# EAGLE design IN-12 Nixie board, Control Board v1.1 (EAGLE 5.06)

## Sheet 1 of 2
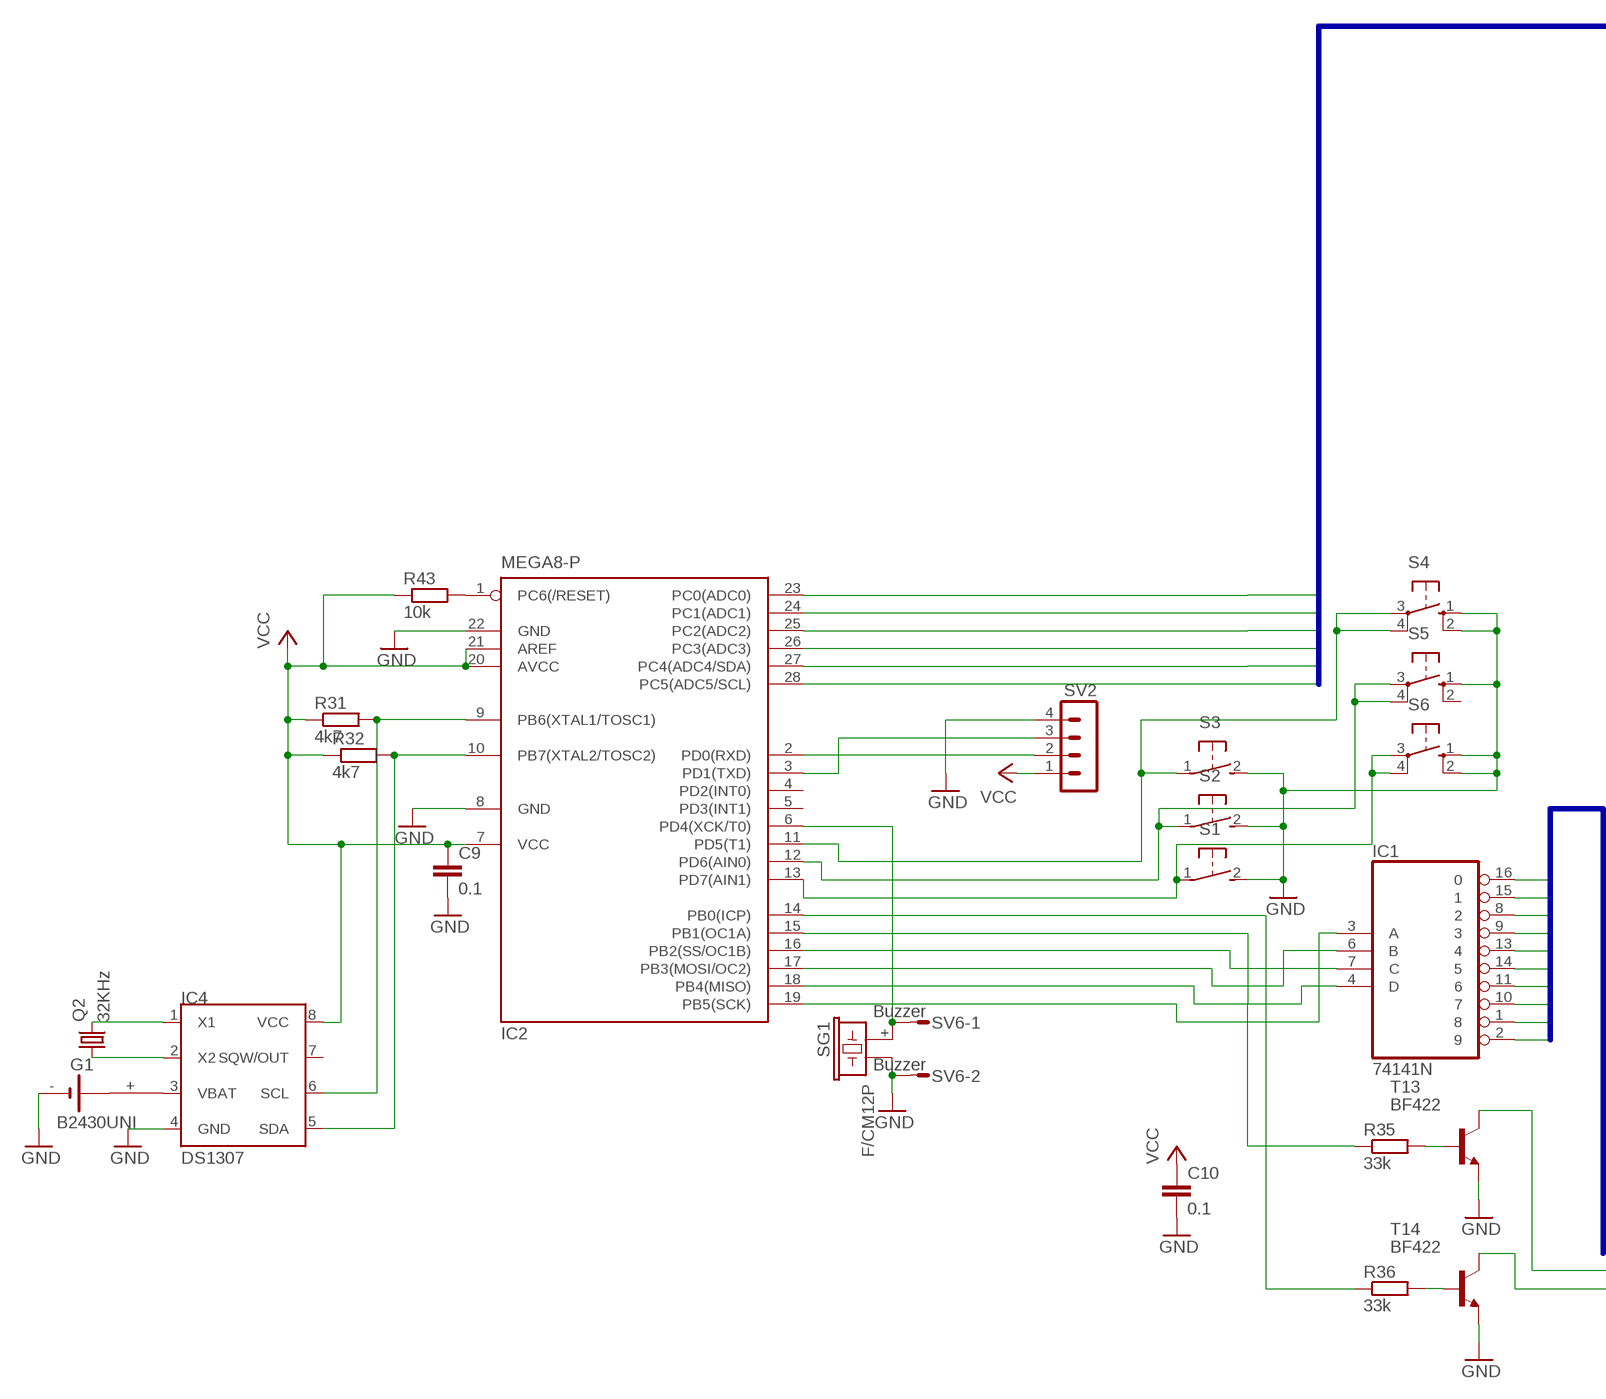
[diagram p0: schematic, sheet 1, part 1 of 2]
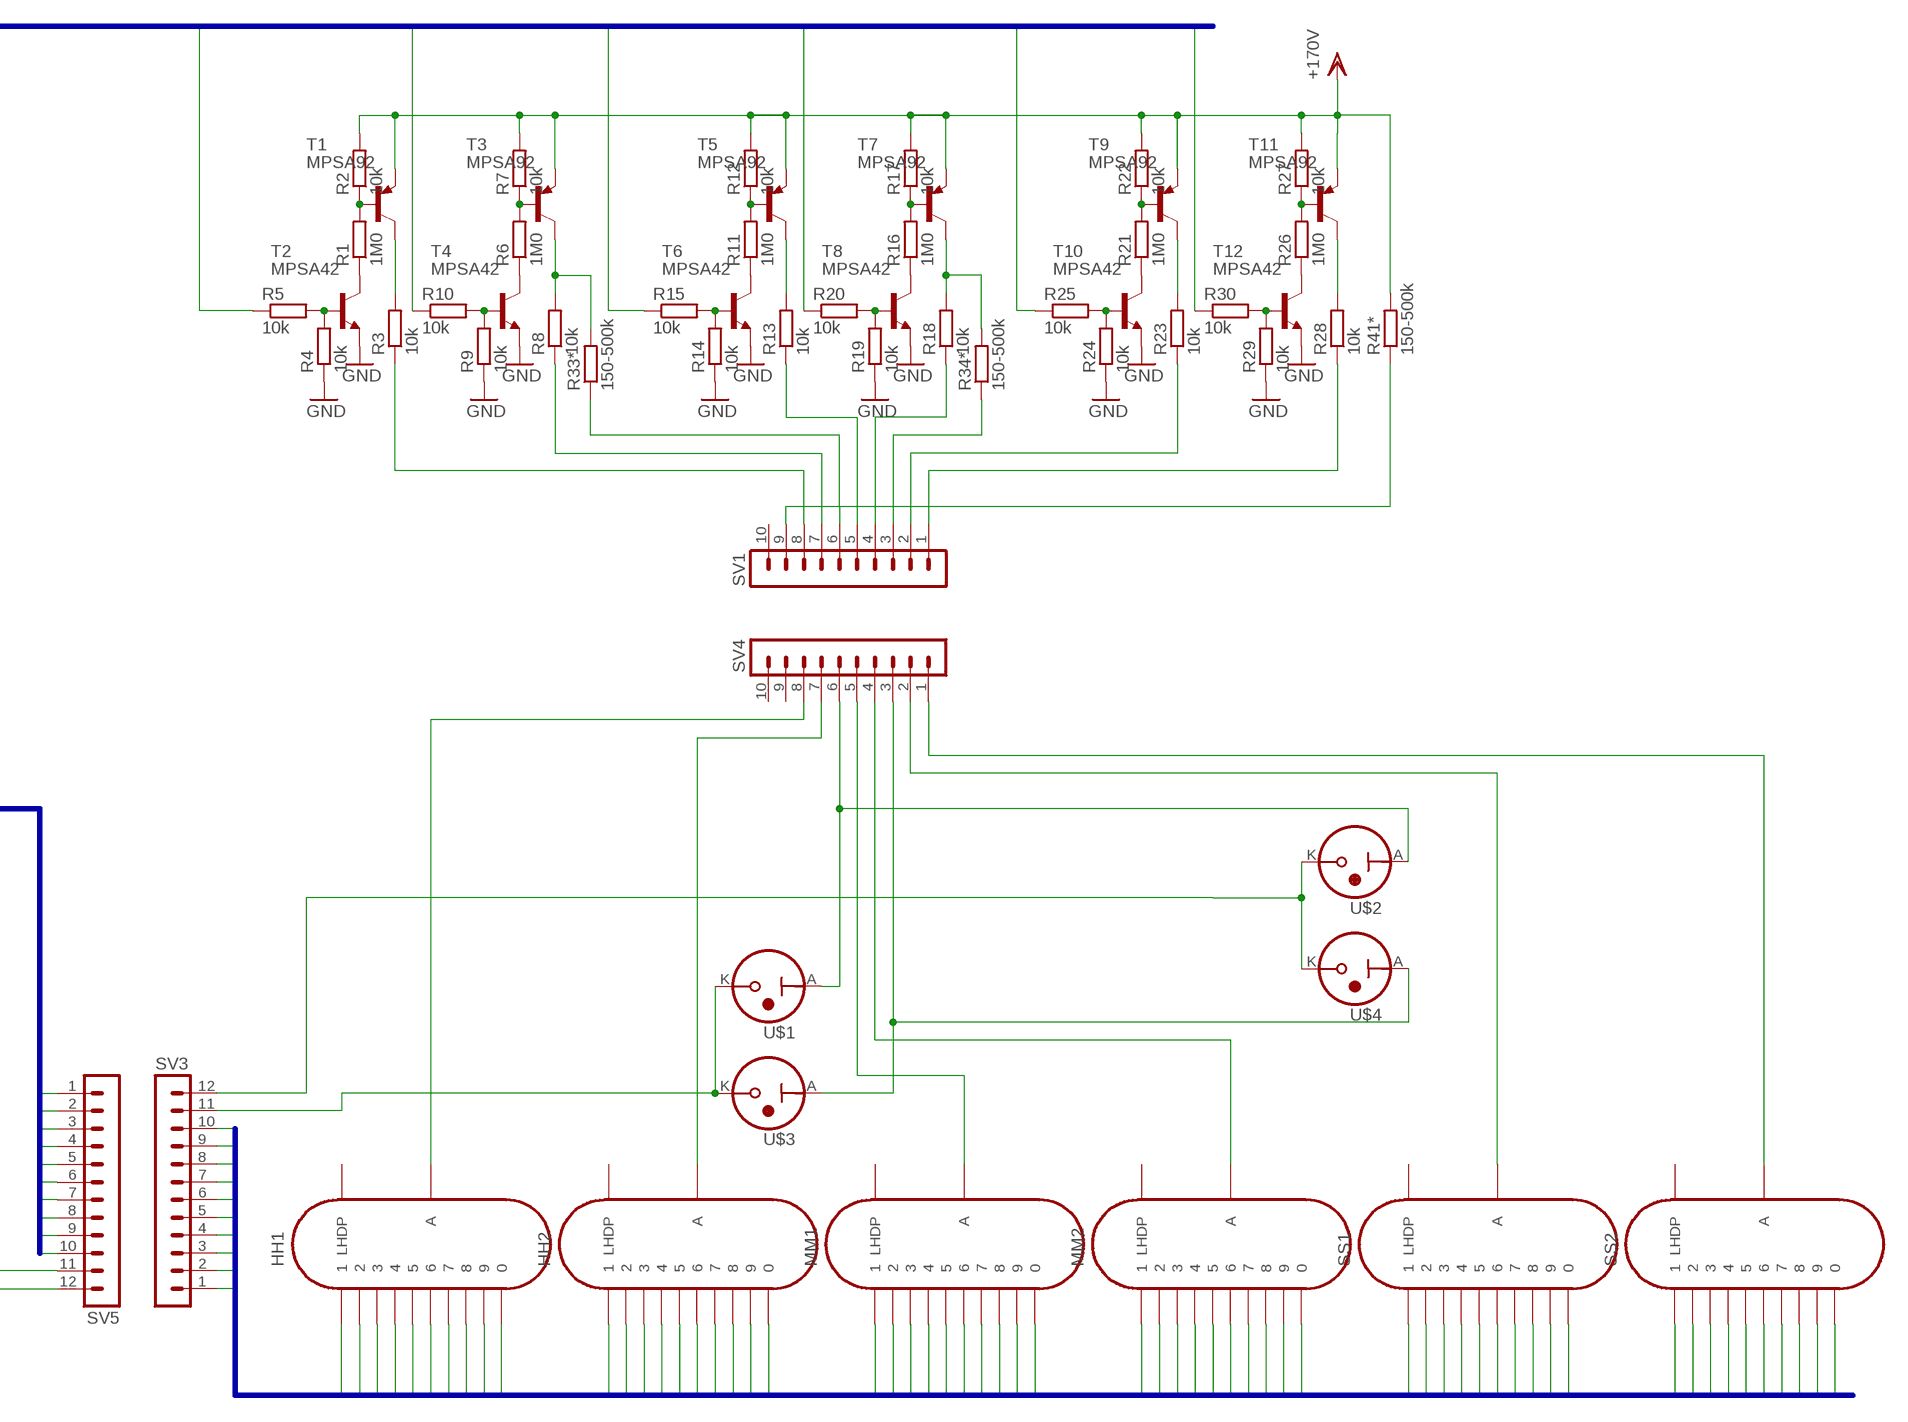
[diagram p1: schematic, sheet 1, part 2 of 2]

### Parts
C9  0.1  C-EUC1206  [C1206]
C10  0.1  C-EUC1206  [C1206]
G1  B2430UNI  [B2430UNI]
HH1  IN-12B  [IN-12]
HH2  IN-12B  [IN-12]
IC1  74141N  [DIL16]
IC2  MEGA8-P  [DIL28-3]
IC4  DS1307  [SOIC-8]
MM1  IN-12B  [IN-12]
MM2  IN-12B  [IN-12]
Q2  32KHz  CRYSTALTC26H  [TC26H]
R1  1M0  R-EU_R1206  [R1206]
R2  10k  R-EU_R1206  [R1206]
R3  10k  R-EU_R1206  [R1206]
R4  10k  R-EU_R1206  [R1206]
R5  10k  R-EU_R1206  [R1206]
R6  1M0  R-EU_R1206  [R1206]
R7  10k  R-EU_R1206  [R1206]
R8  10k  R-EU_R1206  [R1206]
R9  10k  R-EU_R1206  [R1206]
R10  10k  R-EU_R1206  [R1206]
R11  1M0  R-EU_R1206  [R1206]
R12  10k  R-EU_R1206  [R1206]
R13  10k  R-EU_R1206  [R1206]
R14  10k  R-EU_R1206  [R1206]
R15  10k  R-EU_R1206  [R1206]
R16  1M0  R-EU_R1206  [R1206]
R17  10k  R-EU_R1206  [R1206]
R18  10k  R-EU_R1206  [R1206]
R19  10k  R-EU_R1206  [R1206]
R20  10k  R-EU_R1206  [R1206]
R21  1M0  R-EU_R1206  [R1206]
R22  10k  R-EU_R1206  [R1206]
R23  10k  R-EU_R1206  [R1206]
R24  10k  R-EU_R1206  [R1206]
R25  10k  R-EU_R1206  [R1206]
R26  1M0  R-EU_R1206  [R1206]
R27  10k  R-EU_R1206  [R1206]
R28  10k  R-EU_R1206  [R1206]
R29  10k  R-EU_R1206  [R1206]
R30  10k  R-EU_R1206  [R1206]
R31  4k7  R-EU_R1206  [R1206]
R32  4k7  R-EU_R1206  [R1206]
R33*  150-500k  R-EU_R1206  [R1206]
R34*  150-500k  R-EU_R1206  [R1206]
R35  33k  R-EU_R1206  [R1206]
R36  33k  R-EU_R1206  [R1206]
R41*  150-500k  R-EU_R1206  [R1206]
R43  10k  R-EU_R1206  [R1206]
S1  31-XX  [B3F-31XX]
S2  31-XX  [B3F-31XX]
S3  31-XX  [B3F-31XX]
S4  10-XX  [B3F-10XX]
S5  10-XX  [B3F-10XX]
S6  10-XX  [B3F-10XX]
SG1  F/CM12P  [F/CM12P]
SS1  IN-12B  [IN-12]
SS2  IN-12B  [IN-12]
SV1  MA10-1  [MA10-1]
SV2  MA04-1  [MA04-1]
SV3  MA12-1  [MA12-1]
SV4  MA10-1  [MA10-1]
SV5  MA12-1  [MA12-1]
SV6  Buzzer  S02P  [S02P]
T1  MPSA92  MPSA63  [TO92-CBE]
T2  MPSA42  MPSA42-NPN-TO92-CBE  [TO92-CBE]
T3  MPSA92  MPSA63  [TO92-CBE]
T4  MPSA42  MPSA42-NPN-TO92-CBE  [TO92-CBE]
T5  MPSA92  MPSA63  [TO92-CBE]
T6  MPSA42  MPSA42-NPN-TO92-CBE  [TO92-CBE]
T7  MPSA92  MPSA63  [TO92-CBE]
T8  MPSA42  MPSA42-NPN-TO92-CBE  [TO92-CBE]
T9  MPSA92  MPSA63  [TO92-CBE]
T10  MPSA42  MPSA42-NPN-TO92-CBE  [TO92-CBE]
T11  MPSA92  MPSA63  [TO92-CBE]
T12  MPSA42  MPSA42-NPN-TO92-CBE  [TO92-CBE]
T13  BF422  BF422-NPN-TO92-BCE  [TO92-BCE]
T14  BF422  BF422-NPN-TO92-BCE  [TO92-BCE]
U$1  IN-3  [IN-3]
U$2  IN-3  [IN-3]
U$3  IN-3  [IN-3]
U$4  IN-3  [IN-3]

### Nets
0: IC1.8 SV5.10
1: IC1.2 SV5.9
2: IC1.1 SV5.8
3: IC1.9 SV5.7
4: IC1.10 SV5.6
5: IC1.11 SV5.5
6: IC1.13 SV5.4
7: IC1.14 SV5.3
8: IC1.15 SV5.2
9: IC1.16 SV5.1
$NEON1: SV5.11 T13.C
$NEON2: SV5.12 T14.C
GND: C9.2 C10.2 G1.- IC2.8(GND) IC2.22(GND) IC4.4(GND) R4.1 R9.1 R14.1 R19.1 R24.1 R29.1 S1.2(S) S2.2(S) S3.2(S) S4.1(S) S4.2(S1) S5.1(S) S6.1(S) S6.2(S1) SG1.- SV2.4 SV6.2 T2.E T4.E T6.E T8.E T10.E T12.E T13.E T14.E ; also sheet 2
H1: IC2.26(PC3(ADC3)) R5.1
H2: IC2.27(PC4(ADC4/SDA)) R10.1
L0: HH1.0 HH2.0 MM1.0 MM2.0 SS1.0 SS2.0 SV3.10
L1: HH1.1 HH2.1 MM1.1 MM2.1 SS1.1 SS2.1 SV3.9
L2: HH1.2 HH2.2 MM1.2 MM2.2 SS1.2 SS2.2 SV3.8
L3: HH1.3 HH2.3 MM1.3 MM2.3 SS1.3 SS2.3 SV3.7
L4: HH1.4 HH2.4 MM1.4 MM2.4 SS1.4 SS2.4 SV3.6
L5: HH1.5 HH2.5 MM1.5 MM2.5 SS1.5 SS2.5 SV3.5
L6: HH1.6 HH2.6 MM1.6 MM2.6 SS1.6 SS2.6 SV3.4
L7: HH1.7 HH2.7 MM1.7 MM2.7 SS1.7 SS2.7 SV3.3
L8: HH1.8 HH2.8 MM1.8 MM2.8 SS1.8 SS2.8 SV3.2
L9: HH1.9 HH2.9 MM1.9 MM2.9 SS1.9 SS2.9 SV3.1
M1: IC2.28(PC5(ADC5/SCL)) R15.1
M2: IC2.25(PC2(ADC2)) R20.1
N$1: R36.2 T14.B
N$2: R35.2 T13.B
N$3: R28.1 SV1.1
N$4: IC2.14(PB0(ICP)) R36.1
N$5: IC2.15(PB1(OC1A)) R35.1
N$13: SV4.6 U$1.A U$2.A
N$14: MM2.A SV4.4
N$15: SS1.A SV4.2
N$16: MM1.A SV4.5
N$17: R3.2 T1.C
N$18: HH2.A SV4.7
N$20: R1.2 R2.1 T1.B
N$21: R1.1 T2.C
N$22: R4.2 R5.2 T2.B
N$23: HH1.A SV4.8
N$24: R8.2 R33*.2 T3.C
N$25: R6.2 R7.1 T3.B
N$26: R6.1 T4.C
N$27: R9.2 R10.2 T4.B
N$28: R23.1 SV1.2
N$29: R13.2 T5.C
N$30: R11.2 R12.1 T5.B
N$31: R11.1 T6.C
N$32: R14.2 R15.2 T6.B
N$33: SS2.A SV4.1
N$34: R41*.1 SV1.9
N$35: R16.2 R17.1 T7.B
N$36: R16.1 T8.C
N$37: R19.2 R20.2 T8.B
N$38: R34*.1 SV1.3
N$39: R23.2 T9.C
N$40: R21.2 R22.1 T9.B
N$41: R21.1 T10.C
N$42: R24.2 R25.2 T10.B
N$43: R18.1 SV1.4
N$44: R28.2 T11.C
N$45: R26.2 R27.1 T11.B
N$46: R26.1 T12.C
N$47: R29.2 R30.2 T12.B
N$49: R13.1 SV1.5
N$51: SV4.3 U$3.A U$4.A
N$52: R8.1 SV1.7
N$53: R3.1 SV1.8
N$54: IC2.2(PD0(RXD)) SV2.2
N$55: IC2.3(PD1(TXD)) SV2.3
N$56: IC2.13(PD7(AIN1)) S1.1(P) S6.3(P) S6.4(P1)
N$57: IC2.12(PD6(AIN0)) S2.1(P) S5.3(P) S5.4(P1)
N$58: IC2.11(PD5(T1)) S3.1(P) S4.3(P) S4.4(P1)
N$59: IC1.7(C) IC2.16(PB2(SS/OC1B))
N$60: IC1.6(B) IC2.17(PB3(MOSI/OC2))
N$61: IC1.4(D) IC2.18(PB4(MISO))
N$62: IC1.3(A) IC2.19(PB5(SCK))
N$63: IC2.10(PB7(XTAL2/TOSC2)) IC4.5(SDA) R32.2
N$64: IC2.9(PB6(XTAL1/TOSC1)) IC4.6(SCL) R31.2
N$65: IC4.1(X1) Q2.2
N$66: IC4.2(X2) Q2.1
N$67: G1.+ IC4.3(VBAT)
N$68: R33*.1 SV1.6
N$71: IC2.6(PD4(XCK/T0)) SG1.+ SV6.1
N$72: R18.2 R34*.2 T7.C
N$90: IC2.1(PC6(/RESET)) R43.2
NEON1: SV3.12 U$2.K U$4.K
NEON2: SV3.11 U$1.K U$3.K
S1: IC2.24(PC1(ADC1)) R25.1
S2: IC2.23(PC0(ADC0)) R30.1
VCC: C9.1 C10.1 IC2.7(VCC) IC2.20(AVCC) IC2.21(AREF) IC4.8(VCC) R31.1 R32.1 R43.1 SV2.1 ; also sheet 2
VDD: R2.2 R7.2 R12.2 R17.2 R22.2 R27.2 R41*.2 T1.E T3.E T5.E T7.E T9.E T11.E ; supply symbol labelled +170V ; also sheet 2
Unconnected: G1.+@1(+) G1.+@2(+) G1.+@3(+) G1.+@4(+) G1.-@1(-) HH1.LHDP HH2.LHDP IC2.4(PD2(INT0)) IC2.5(PD3(INT1)) IC4.7(SQW/OUT) MM1.LHDP MM2.LHDP S5.2(S1) SS1.LHDP SS2.LHDP SV1.10 SV4.9 SV4.10

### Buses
H1,H2,M1,M2,S1,S2
0,1,2,3,4,5,6,7,8,9,L1,L2
L0,L1,L2,L3,L4,L5,L6,L7,L8,L9

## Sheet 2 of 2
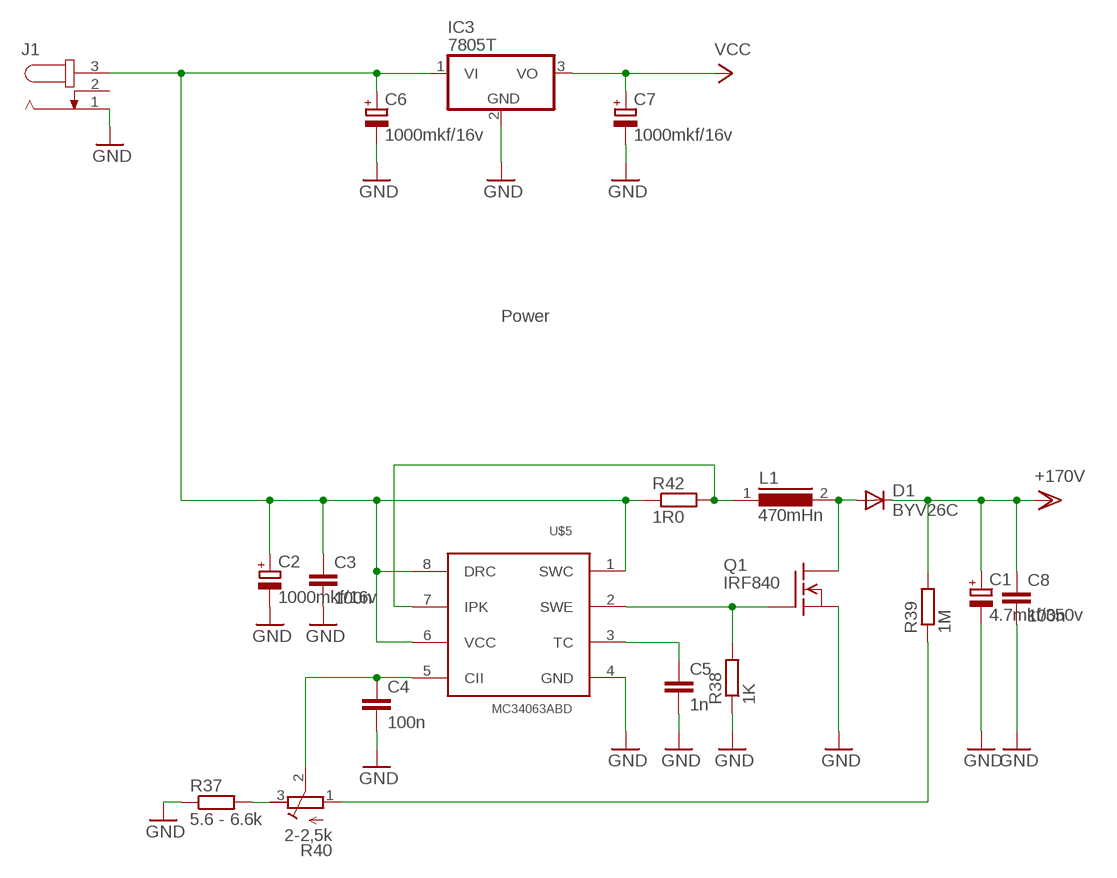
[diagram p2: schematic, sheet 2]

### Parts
C1  4.7mkf/350v  CPOL-EUE5-10.5  [E5-10,5]
C2  1000mkf/16v  CPOL-EUE5-8.5  [E5-8,5]
C3  100n  C-EU050-025X075  [C050-025X075]
C4  100n  C-EU050-025X075  [C050-025X075]
C5  1n  C-EU050-025X075  [C050-025X075]
C6  1000mkf/16v  CPOL-EUE5-8.5  [E5-8,5]
C7  1000mkf/16v  CPOL-EUE5-8.5  [E5-8,5]
C8  100n  C-EU050-025X075  [C050-025X075]
D1  BYV26C  BYV28  [SOD64-10]
IC3  7805T  [TO220H]
J1  JACK-PLUG1  [SPC4078]
L1  470mHn  B82131  [SUKW1-17]
Q1  IRF840  [TO220]
R37  5.6 - 6.6k  R-EU_R3216  [R3216]
R38  1K  R-EU_R3216  [R3216]
R39  1M  R-EU_R3216  [R3216]
R40  2-2,5k  R-TRIMM3339P  [RTRIM3339P]
R42  1R0  R-EU_M2309  [M2309]
U$5  MC34063ABD  [SO08]

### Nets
GND: C1.- C2.- C3.2 C4.2 C5.2 C6.- C7.- C8.2 IC3.2(GND) J1.1 Q1.3(S) R37.1 R38.1 U$5.4(GND) ; also sheet 1
N$6: C4.1 R40.2(S) U$5.5(CII)
N$8: Q1.1(G) R38.2 U$5.2(SWE)
N$9: C5.1 U$5.3(TC)
N$12: L1.1 R42.2 U$5.7(IPK)
N$48: R37.2 R40.3(A)
N$50: R39.1 R40.1(E)
N$92: D1.A L1.2 Q1.2(D)
VCC: C7.+ IC3.3(VO) ; also sheet 1
VCC+12: C2.+ C3.1 C6.+ IC3.1(VI) J1.3 R42.1 U$5.1(SWC) U$5.6(VCC) U$5.8(DRC)
VDD: C1.+ C8.1 D1.C R39.2 ; supply symbol labelled +170V ; also sheet 1
Unconnected: J1.2

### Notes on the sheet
- Power

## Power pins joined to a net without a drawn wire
GND: IC1.12(GND)
VCC: IC1.5(VCC)

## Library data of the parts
C1 C2 C6 C7 = rcl:CPOL-EU: POLARIZED CAPACITOR, European symbol
C3-C5 C8 = rcl:C-EU: CAPACITOR, European symbol
C9 C10 = resistor:C-EU: CAPACITOR, European symbol
D1 = diode:BYV28: DIODE
G1 = battery:B2430UNI: LI BATTERY
HH1 HH2 MM1 MM2 SS1 SS2 = russian-nixies:IN-12B: IN-12B: medium numeric topview nixie tube
IC1 = 74xx-eu:74*141: BCD to decimal DECODER/DRIVER
IC2 = atmel:MEGA8-P: MICROCONTROLLER 8 Kbytes FLASH, 1 kbytes SRAM, 512 bytes EEPROM, USART, 4-channel 10 bit ADC, 2-channel 8 bit ADC Pin compatible with Atmega48, ATMega88, ATMega168 Source: avr.lbr
IC3 = linear:78*: Positive VOLTAGE REGULATOR Source: http://cache.national.com/ds/LM/LM78L05.pdf http://www.fairchildsemi.com/ds/LM/LM7805.pdf
IC4 = dallas-1:DS1307: I2C Serial RTC w/56 bytes battery backed RAM
J1 = con-jack:JACK-PLUG: DC POWER JACK Power Jack, DC, Right Angle, Through Hole, Rated 5A at 16VDC, PC Terminals Distributor: Farnell (www.Farnell.de) Drawing: 84N1161.pdf / 84N1162.pdf Manufacturer: SPC Technology (www.spctechnology.com) Type: SPC4077 / SPC 4078
L1 = inductors:B82131: INDUCTOR
Q1 = transistor-fet:IRF840: N-Channel Enhancement MOSFET (HEXFET); 500V; 8A; 0,85Ohm
Q2 = crystal:CRYSTAL: CRYSTAL
R1-R32 R33* R34* R35-R39 R41* R42 R43 = resistor:R-EU_: RESISTOR, European symbol
R40 = resistor:R-TRIMM: Trimm resistor
S1-S3 = switch-omron:31-XX: OMRON SWITCH
S4-S6 = switch-omron:10-XX: OMRON SWITCH
SG1 = buzzer:F/CM12P: BUZZER
SV1 SV4 = con-lstb:MA10-1: PIN HEADER
SV2 = con-lstb:MA04-1: PIN HEADER
SV3 SV5 = con-lstb:MA12-1: PIN HEADER
SV6 = con-amp-mt:S02P: AMP MT CONNECTOR
T1 T3 T5 T7 T9 T11 = transistor-pnp:MPSA63*: PNP Transistror
T2 T4 T6 T8 T10 T12-T14 = transistor:*-NPN-: NPN Transistror BF959 corrected 2008.03.06
U$1-U$4 = russian-nixies:IN-3: IN-3: nixie bulb
U$5 = st-microelectronics:MC34063: DC-DC Converter Control Circuits

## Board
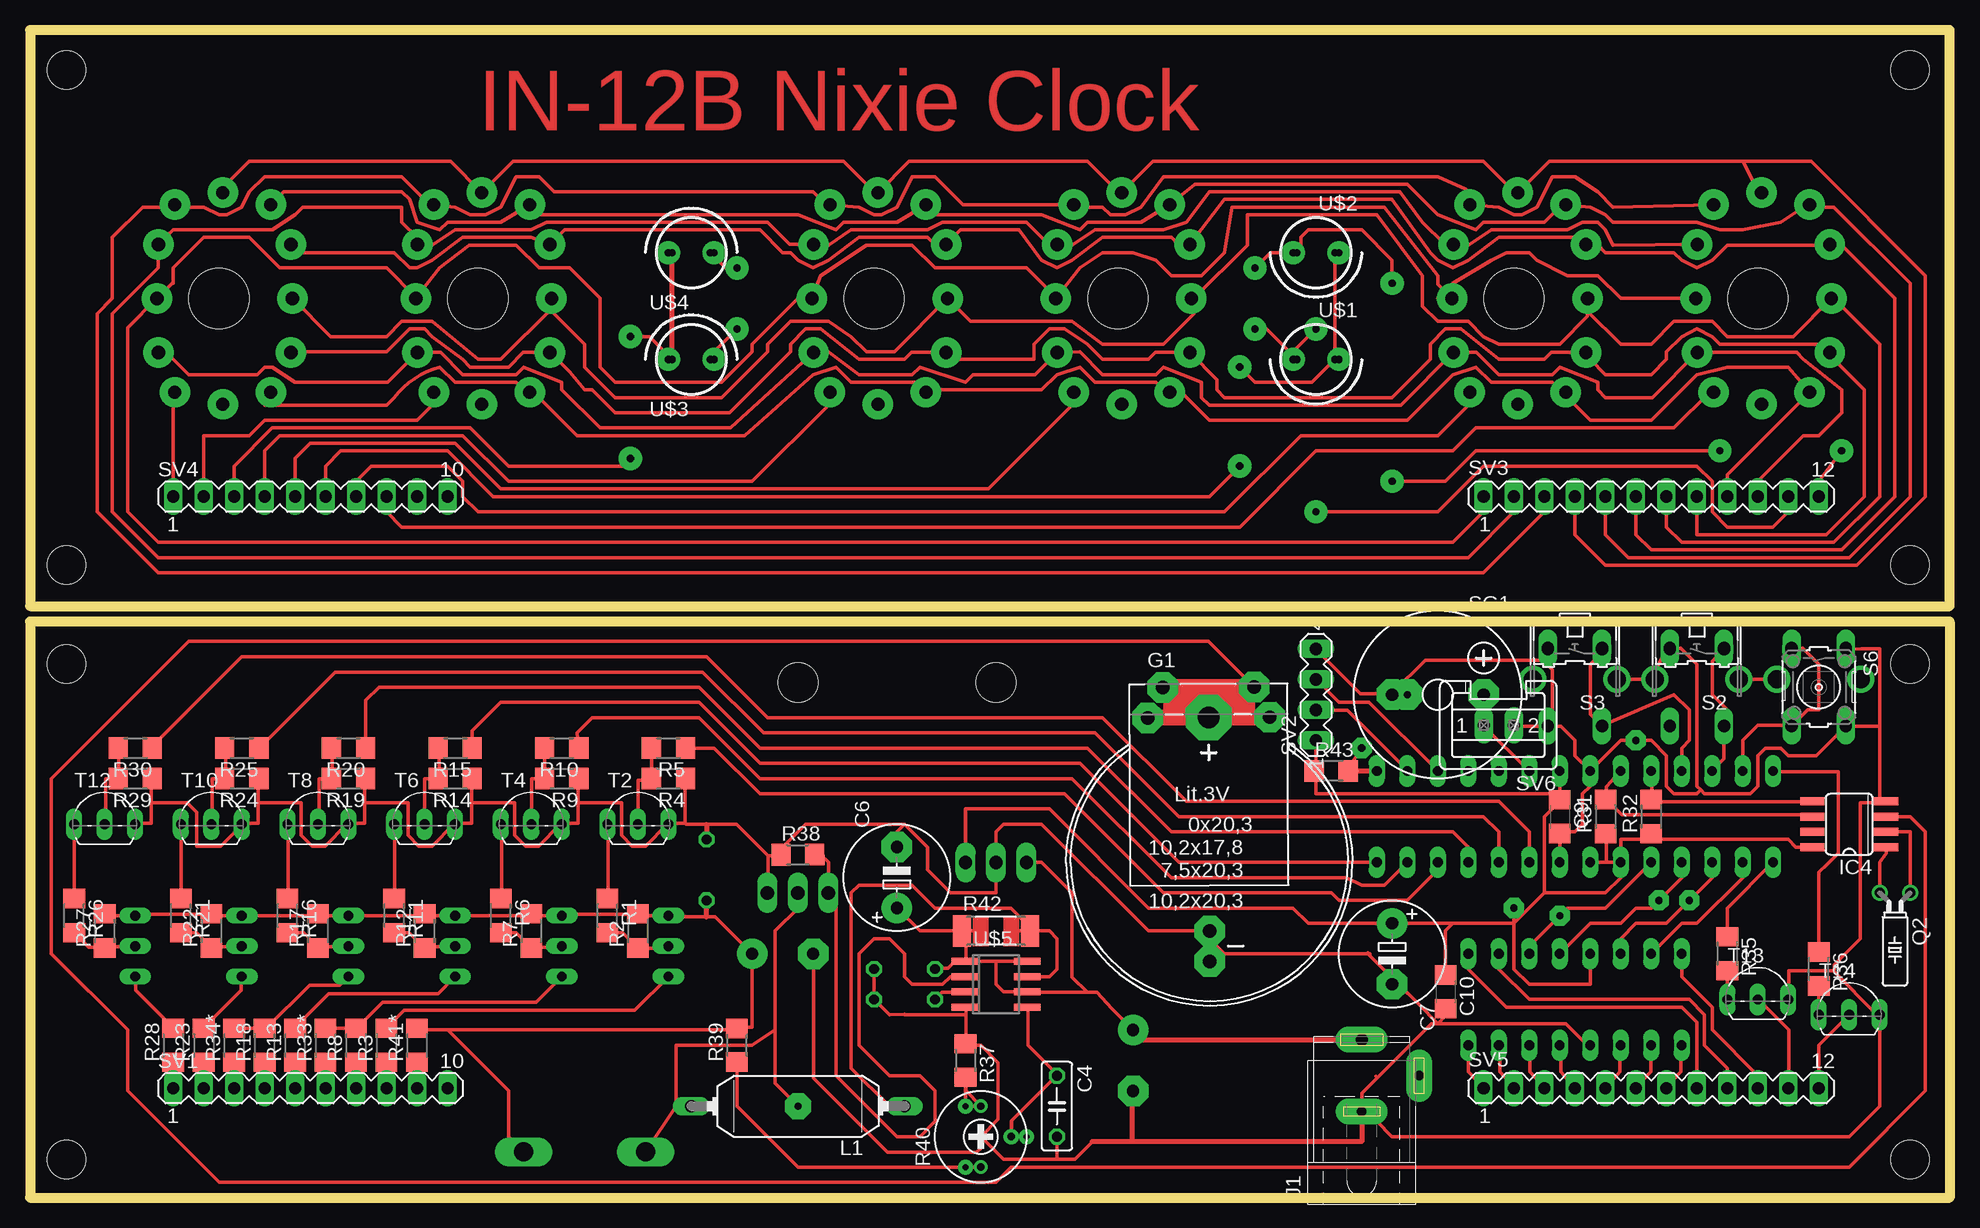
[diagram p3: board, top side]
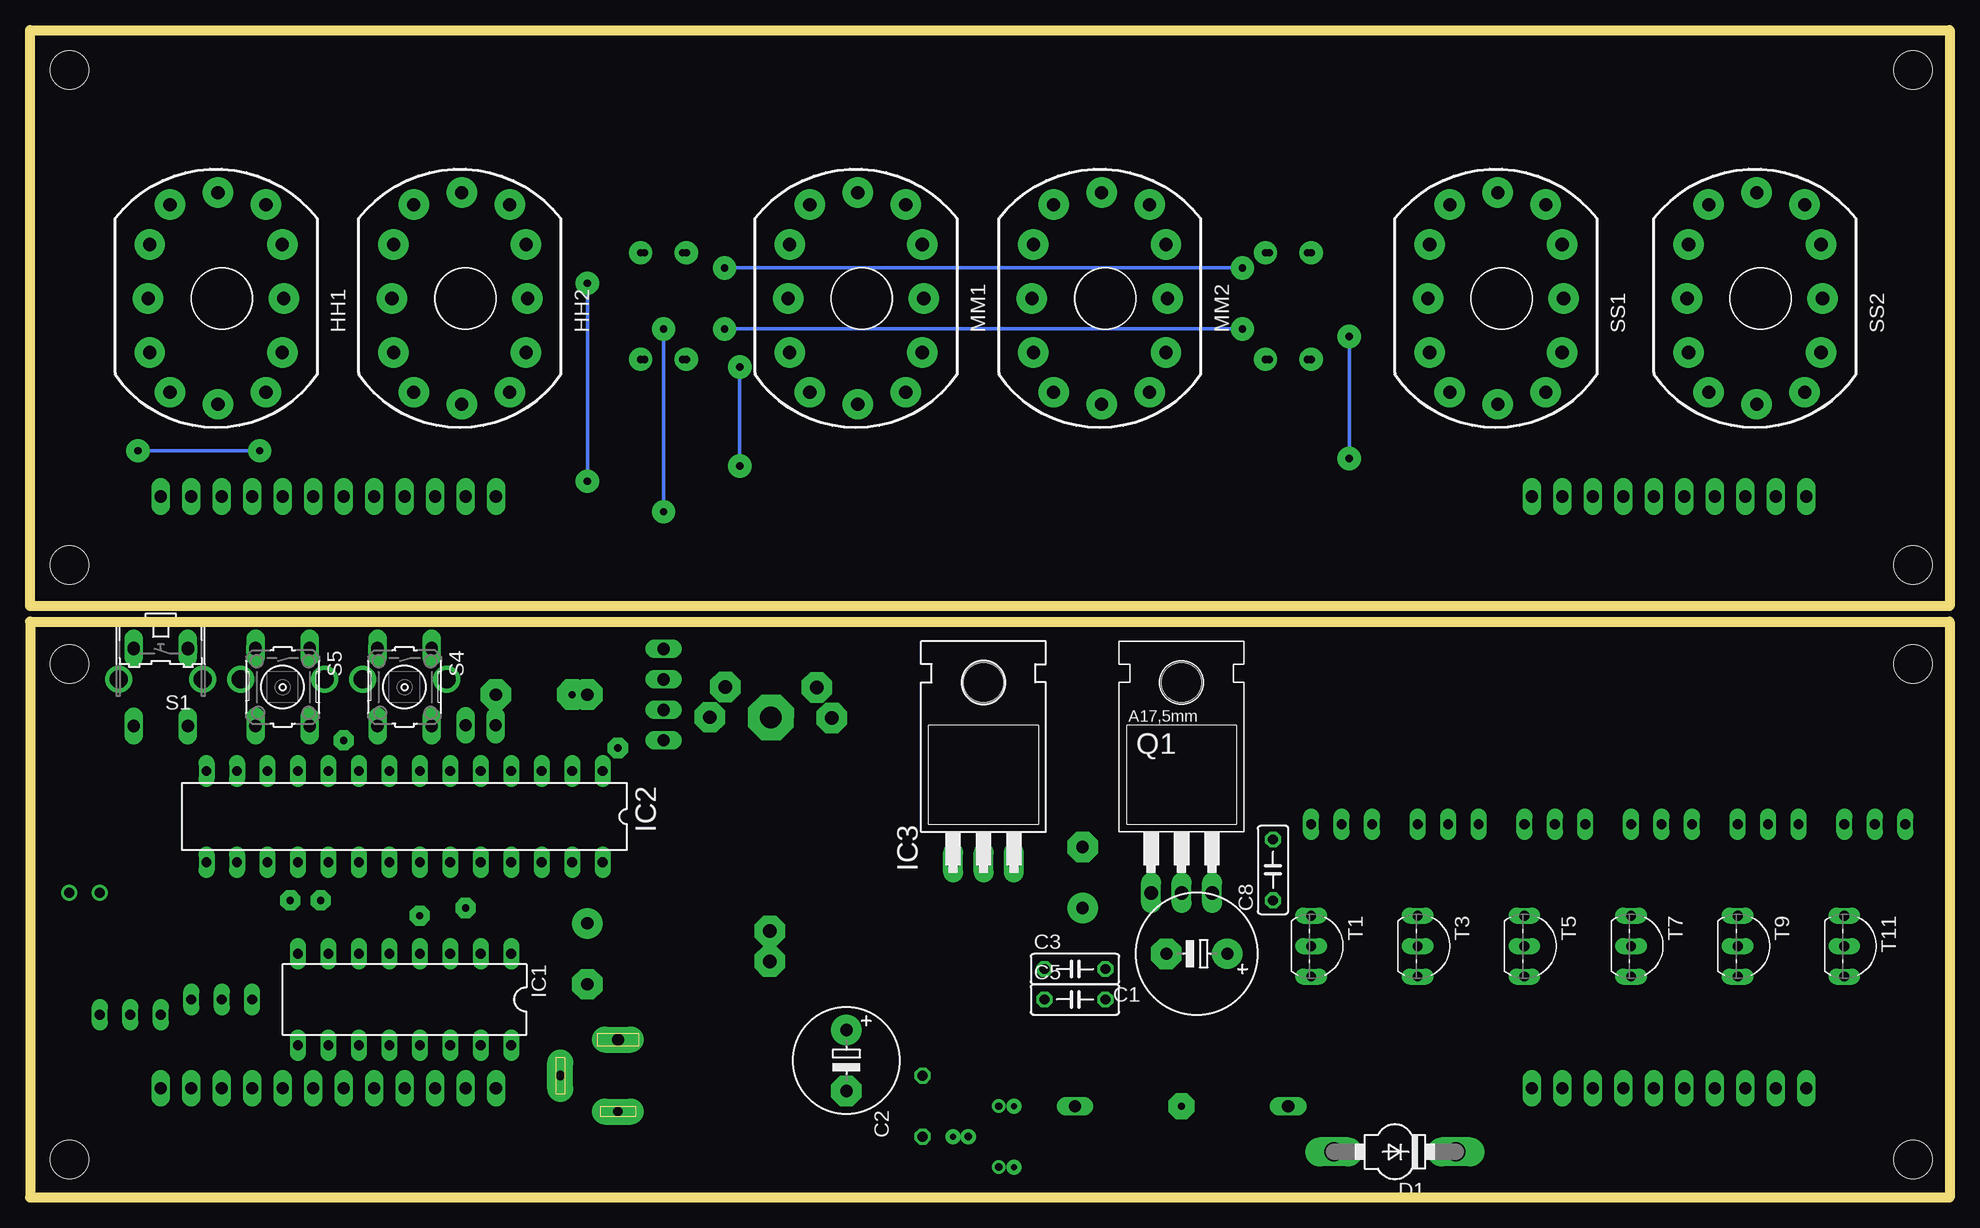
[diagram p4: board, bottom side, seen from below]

Size 160 x 97.3 mm. Coordinates in mm from the lower left corner, seen from the top.
Outline: 0,49.3 160,49.3 160,97.3 0,97.3 0,49.3
Outline: 160,48 0,48 0,0 160,0 160,48
Copper layers (1*16): Top 0.035mm / dielectric 1.5mm / Bottom 0.035mm
Design rules "default *": minimum track width 12mil, minimum drill 12mil, track to track 12mil, track to pad 12mil, pad to pad 8mil, via to via 8mil, smd to smd 8mil, copper to edge 10mil, drill to drill 8mil, minimum pad ring 10mil, minimum via ring 8mil, stop-mask expansion 4mil, vias tented up to drill 0mil, thermal gap 10mil
Holes 3.2 mm at 3.05,52.7 3.05,93.98 156.72,52.7 156.72,93.98 3.05,44.45 3.05,3.17 156.72,44.45 156.72,3.17

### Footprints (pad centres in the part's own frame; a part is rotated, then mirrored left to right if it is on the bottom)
E5-10,5 = drill 1.016 pad 2.54: + -2.54,0 | drill 1.016 pad 2.54 octagon: - 2.54,0
E5-8,5 = drill 1.016 pad 2.54: + -2.54,0 | drill 1.016 pad 2.54 octagon: - 2.54,0
C050-025X075 = drill 0.813 octagon: 1 -2.54,0; 2 2.54,0
C1206 = smd 1.6 x 1.8: 1 -1.4,0; 2 1.4,0
SOD64-10 = drill 1.6 long: A 5.08,0; C -5.08,0
B2430UNI = drill 1.118 pad 2.54 octagon: + 3.81,14.605; +@1 -3.81,14.605; +@2 -5.08,12.065; +@3 5.08,12.065; - 0,-5.715; -@1 0,-8.255 | drill 1.803 pad 3.81 octagon: +@4 0,12.065
IN-12 = drill 1.1 pad 2.54: 0 5.048,-4.5; 1 -4.317,-7.817; 2 -6,-4.5; 3 -6.127,0; 4 -6,4.5; 5 -4.317,7.817; 6 -0.318,8.818; 7 3.683,7.817; 8 5.048,4.5; 9 5.175,0; A 3.683,-7.817; LHDP -0.318,-8.818 | hole 5: 0,0
DIL16 = drill 0.813 long: 1 -8.89,-3.81; 2 -6.35,-3.81; 3 -3.81,-3.81; 4 -1.27,-3.81; 5 1.27,-3.81; 6 3.81,-3.81; 7 6.35,-3.81; 8 8.89,-3.81; 9 8.89,3.81; 10 6.35,3.81; 11 3.81,3.81; 12 1.27,3.81; 13 -1.27,3.81; 14 -3.81,3.81; 15 -6.35,3.81; 16 -8.89,3.81
DIL28-3 = drill 0.813 long: 1 -16.51,-3.81; 2 -13.97,-3.81; 3 -11.43,-3.81; 4 -8.89,-3.81; 5 -6.35,-3.81; 6 -3.81,-3.81; 7 -1.27,-3.81; 8 1.27,-3.81; 9 3.81,-3.81; 10 6.35,-3.81; 11 8.89,-3.81; 12 11.43,-3.81; 13 13.97,-3.81; 14 16.51,-3.81; 15 16.51,3.81; 16 13.97,3.81; 17 11.43,3.81; 18 8.89,3.81; 19 6.35,3.81; 20 3.81,3.81; 21 1.27,3.81; 22 -1.27,3.81; 23 -3.81,3.81; 24 -6.35,3.81; 25 -8.89,3.81; 26 -11.43,3.81; 27 -13.97,3.81; 28 -16.51,3.81
TO220H = drill 1.118 long: 1 -2.54,-10.16; 2 0,-10.16; 3 2.54,-10.16 | hole 3.302: 0,4.826
SOIC-8 = smd 2.032 x 0.66: 1 -3.073,1.27; 2 -3.073,0; 3 -3.073,-1.27; 4 -3.073,-2.54; 5 3.073,-2.54; 6 3.073,-1.27; 7 3.073,0; 8 3.073,1.27
SPC4078 = drill 0.8 pad 2.184 long: 1 -3,0; 2 0,-4.8 | drill 1 pad 2.184 long: 3 3,0
SUKW1-17 = drill 1.016 long: 1 -8.89,0; 2 8.89,0
TO220 = drill 1.118 long: 1 -2.54,-6.35; 2 0,-6.35; 3 2.54,-6.35 | hole 3.302: 0,11.176
TC26H = drill 0.813: 1 -1.27,0; 2 1.27,0
R1206 = smd 1.6 x 1.803: 1 -1.422,0; 2 1.422,0
R3216 = smd 1.6 x 1.8: 1 -1.4,0; 2 1.4,0
RTRIM3339P = drill 0.61: 1 -2.54,0; 2 0,-2.54; 3 2.54,0
M2309 = smd 1.5 x 2.6: 1 -2.85,0; 2 2.85,0
B3F-31XX = drill 1.016 octagon: 1 -2.261,-1.245; 2 2.261,-1.245 | drill 1.499 pad 2.159: 3 -3.505,1.245; 4 3.505,1.245
B3F-10XX = drill 1.016 long: 1 -3.251,2.261; 2 3.251,2.261; 3 -3.251,-2.261; 4 3.251,-2.261
F/CM12P = drill 1.016 pad 2.54 octagon: + 3.81,0; - -3.81,0
MA10-1 = drill 1.016 long: 1 -11.43,0; 2 -8.89,0; 3 -6.35,0; 4 -3.81,0; 5 -1.27,0; 6 1.27,0; 7 3.81,0; 8 6.35,0; 9 8.89,0; 10 11.43,0
MA04-1 = drill 1.016 long: 1 -3.81,0; 2 -1.27,0; 3 1.27,0; 4 3.81,0
MA12-1 = drill 1.016 long: 1 -13.97,0; 2 -11.43,0; 3 -8.89,0; 4 -6.35,0; 5 -3.81,0; 6 -1.27,0; 7 1.27,0; 8 3.81,0; 9 6.35,0; 10 8.89,0; 11 11.43,0; 12 13.97,0
S02P = drill 1.016 long: 1 1.25,0; 2 -1.25,0
TO92-CBE = drill 0.813 long: B 0,0; C 2.54,0; E -2.54,0
TO92-CBE' = drill 0.813 long: B 0,0; C -2.54,0; E 2.54,0
TO92-BCE = drill 0.813 long: B -2.54,0; C 0,0; E 2.54,0
IN-3 = drill 0.6 octagon: A -1.587,0; K 1.587,0
SO08 = smd 0.6 x 2.2: 1 -1.905,-2.6; 2 -0.635,-2.6; 3 0.635,-2.6; 4 1.905,-2.6; 5 1.905,2.6; 6 0.635,2.6; 7 -0.635,2.6; 8 -1.905,2.6

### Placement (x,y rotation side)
C1  62.74,20.32 180 bottom
C2  91.95,11.43 270 bottom
C3  72.9,19.05 0 bottom
C4  85.6,7.62 270 top
C5  72.9,16.51 0 bottom
C6  72.27,26.67 90 top
C7  113.54,20.32 270 top
C8  56.39,27.3 90 bottom
C9  127.51,31.75 270 top
C10  117.99,17.14 270 top
D1  46.23,3.81 180 bottom
G1  98.3,27.94 0.3 top
HH1  144.02,74.93 0 bottom
HH2  123.7,74.93 0 bottom
IC1  128.78,16.51 180 bottom
IC2  128.78,31.75 180 bottom
IC3  80.52,38.1 0 bottom
IC4  151.64,30.48 180 top
J1  111,10.16 90 top
L1  64.01,7.62 180 top
MM1  90.68,74.93 0 bottom
MM2  70.36,74.93 0 bottom
Q1  64.01,31.75 0 bottom
Q2  155.45,25.4 180 top
R1  48.14,23.5 270 top
R2  50.67,22.23 90 top
R3  29.72,12.7 90 top
R4  53.22,34.92 180 top
R5  53.22,37.47 180 top
R6  39.24,23.5 270 top
R7  41.78,22.23 90 top
R8  27.18,12.7 90 top
R9  44.33,34.92 180 top
R10  44.33,37.47 180 top
R11  30.35,23.5 270 top
R12  32.9,22.23 90 top
R13  22.1,12.7 90 top
R14  35.44,34.92 180 top
R15  35.44,37.47 180 top
R16  21.47,23.5 270 top
R17  24.01,22.23 90 top
R18  19.56,12.7 90 top
R19  26.55,34.92 180 top
R20  26.55,37.47 180 top
R21  12.57,23.5 270 top
R22  15.11,22.23 90 top
R23  14.48,12.7 90 top
R24  17.66,34.92 180 top
R25  17.66,37.47 180 top
R26  3.68,23.5 270 top
R27  6.23,22.23 90 top
R28  11.94,12.7 90 top
R29  8.77,34.92 180 top
R30  8.77,37.47 180 top
R31  131.32,31.75 90 top
R32  135.13,31.75 90 top
R33*  24.64,12.7 90 top
R34*  17.02,12.7 90 top
R35  141.48,20.32 270 top
R36  149.1,19.05 270 top
R37  77.98,11.43 270 top
R38  64.01,28.57 0.2 top
R39  58.93,12.7 90 top
R40  79.25,5.08 90 top
R41*  32.26,12.7 90 top
R42  80.52,22.23 0 top
R43  108.46,35.56 0 top
S1  149.1,44.45 180 bottom
S2  138.94,44.45 180 top
S3  128.78,44.45 180 top
S4  128.78,42.55 270 bottom
S5  138.94,42.55 270 bottom
S6  149.1,42.55 270 top
SG1  117.35,41.91 0 top
SS1  37.34,74.93 0 bottom
SS2  15.75,74.93 0 bottom
SV1  23.37,9.12 0 top
SV2  107.19,41.91 90 top
SV3  135.13,58.42 0 top
SV4  23.37,58.42 0 top
SV5  135.13,9.12 0 top
SV6  122.43,39.37 180 top
T1  53.22,20.95 270 bottom
T2  MPSA42  [TO92-CBE']  50.67,31.11 0 top
T3  44.33,20.95 270 bottom
T4  MPSA42  [TO92-CBE']  41.78,31.11 0 top
T5  35.44,20.95 270 bottom
T6  MPSA42  [TO92-CBE']  32.9,31.11 0 top
T7  26.55,20.95 270 bottom
T8  MPSA42  [TO92-CBE']  24.01,31.11 0 top
T9  17.66,20.95 270 bottom
T10  MPSA42  [TO92-CBE']  15.11,31.11 0 top
T11  8.77,20.95 270 bottom
T12  MPSA42  [TO92-CBE']  6.23,31.11 0 top
T13  144.02,16.51 0 top
T14  151.64,15.24 0 top
U$1  107.19,69.85 180 top
U$2  107.19,78.74 180 top
U$3  55.12,69.85 0 top
U$4  55.12,78.74 0 top
U$5  80.52,17.78 270 top

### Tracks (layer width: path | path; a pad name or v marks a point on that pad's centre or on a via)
0
  Top 0.305: IC1.8 137.67,18.41 140.21,15.88 140.21,13.97 144.02,10.16 SV5.10
1
  Top 0.305: SV5.9 141.48,10.79 139.57,12.7 139.57,15.24 138.31,16.51 124.97,16.51 122.43,19.05 IC1.2
2
  Top 0.305: IC1.1 119.89,19.05 123.06,15.88 137.67,15.88 138.94,14.61 SV5.8
3
  Top 0.305: IC1.9 137.6,12.7 137.6,10.47 136.4,9.2 SV5.7
4
  Top 0.305: IC1.10 135.1,12.7 135.1,10.47 133.9,9.2 SV5.6
5
  Top 0.305: IC1.11 132.5,12.7 132.5,10.47 131.4,9.2 SV5.5
6
  Top 0.305: IC1.13 127.6,12.7 127.6,10.47 128.7,9.2 SV5.4
7
  Top 0.305: IC1.14 125,12.7 125,10.47 126.2,9.2 SV5.3
8
  Top 0.305: IC1.15 122.5,12.7 122.5,10.47 123.7,9.2 SV5.2
9
  Top 0.305: IC1.16 119.9,10.47 121.1,9.2 SV5.1
$NEON1
  Top 0.305: T13.C 144.1,16.5 146.6,14 146.6,9.2 SV5.11
$NEON2
  Top 0.305: T14.C 149.1,12.7 SV5.12
GND  (via drill 0.6, 0.6 pad 1.68)
  Top 0.305: U$5.4 78,15.8 78,15.24 | 78,15.24 72.9,15.24 72.9,15.3 71.63,15.23 C5.2 C3.2 | 78,15.24 78,12.9 R37.1 78,12.7 78,12.4 | C1.- 65.3,20.3 65.3,9.93 71.47,3.77 78.89,3.77 | 85.6,3.2 82.2,3.2 | 85.6,3.2 87.1,3.2 88.56,4.66 | IC1.12 129.8,12.7 128,14.5 117.35,14.5 | 111,7.62 111,8.7 112.3,10 | 117.35,14.5 116.8,14.5 112.3,10 | 112.3,10 112.2,10.1 | 80.5,29.2 80.4,29.09 | 80.5,29.2 80.52,29.21 | R38.1 62.7,28.7 | 85.6,3.2 C4.2 | 154.18,36.09 154.18,39.37 154.18,45.72 152.91,45.72 | 111.67,20.18 111.7,20.2 | S4.1 126.5,45.8 | S5.1 136.7,45.7 S2.2 | 98.3,22.2 G1.- 93.22,22.23 84.33,31.11 81.16,31.11 80.52,30.48 IC3.2 | 150.3,18.9 146.6,18.9 146.6,16.6 T13.E | 150.3,18.9 153.9,15.3 T14.E 154.18,7.62 151.64,5.08 113.54,5.08 112.27,6.35 | SV6.2 123.7,39.3 126.4,39.3 S4.2 126.9,39.4 126.9,44 126,44.9 S4.1 | S3.2 126.5,45.7 S4.1 | 150.3,18.9 150.4,19 150.4,19.4 152.56,21.57 152.56,32.9 154.1,32.9 IC4.4 | IC3.2 80.52,25.4 76.71,25.4 74.81,27.3 74.81,29.21 72.9,31.11 | 72.9,31.11 64.64,31.11 62.74,29.21 62.74,28.7 R38.1 | 80.5,29.2 IC3.2 | C6.- 72.27,30.48 72.9,31.11 | 111.5,20.32 111.5,20.4 111.55,20.3 | 61.5,28.5 61.5,25.4 Q1.3 | 61.5,28.5 62.5,28.5 R38.1 | 54.6,31.2 54.6,34.9 R4.1 | v53.3,31.2 54.6,31.2 | 61.5,28.5 58.9,31.1 56.39,31.1 54.7,31.1 54.6,31.2 | 45.7,32.9 45.7,31.2 v44.4,31.2 | 45.7,32.9 45.7,34.9 R9.1 | 36.8,32.9 36.8,31.2 v35.5,31.2 | 36.8,32.9 36.8,34.9 R14.1 | 27.9,32.9 27.9,31.2 v26.6,31.2 | 27.9,32.9 27.9,34.9 R19.1 | 10.1,32.9 10.1,31.2 v8.8,31.2 | 10.1,32.9 10.1,34.9 R29.1 | 19,32.9 19,31.2 v17.7,31.2 | 19,32.9 19,34.9 R24.1 | v17.6,31 15.9,29.3 13.9,29.3 13.9,32.1 13.1,32.9 10.1,32.9 | v26.4,31.1 24.6,29.3 23.5,29.3 22.6,30.2 22.6,32.9 19,32.9
  Top 0.305: v35.3,31.1 33.5,29.3 32.4,29.3 31.5,30.2 31.5,32.9 27.9,32.9 | v44.2,31.1 42.4,29.3 41.3,29.3 40.4,30.2 40.4,32.9 36.8,32.9 | v53.1,31.1 51.3,29.3 50.2,29.3 49.3,30.2 49.3,32.9 45.7,32.9 | 130.05,34.29 129.41,33.66 129.41,31.11 128.78,30.48 127.64,30.48 C9.2 IC2.22 | C10.2 117.99,15.13 117.35,14.5 | SV2.4 107.2,45.7 110.9,42 113.5,42 SG1.- 113.6,42.1 116.3,44.8 125.9,44.8 S4.1
  Top 0.306: 115.71,16.14 111.67,20.18 111.55,20.3 | 115.71,16.14 117.35,14.5 | 111.7,20.32 111.5,20.32 99.57,20.32 98.3,21.59 98.3,22.2 | R37.1 78.11,12.7 79.25,12.7 80.7,11.25 80.7,6.53 79.25,5.08 | C7.- 114.07,17.78 115.71,16.14 | 91.9,8 91.9,8.84 C2.- | IC4.4 154.18,33.02 154.18,36.09 | 111,7.62 J1.1 | S4.2 127.59,39.29 128.78,38.1 128.78,36.83 IC2.8 | S6.1 S1.2 152.66,45.72 152.91,45.72 | 154.18,39.37 154.1,39.29 S6.2 148.9,36.83 146.56,36.83 145.93,37.47 144.66,37.47 144.02,36.83 144.02,34.29 143.38,33.66 139.57,33.66 139.26,33.97 | 139.26,33.97 138.94,34.29 138.94,44.45 137.59,45.8 S5.1 | IC2.8 130.05,34.29 | IC2.8 132.59,38.1 v133.86,38.1 135.13,38.1 136.4,36.83 136.4,34.29 137.03,33.66 138.94,33.66 139.26,33.97 | 79.25,5.08 79.25,4.12 78.89,3.77 | 82.2,3.2 81.13,3.2 79.25,5.08
  Top 0.4: 111,7.62 112.27,6.35
  Top 0.406: 91.95,4.66 111,4.66 J1.1 | 91.95,4.66 88.56,4.66 | 91.9,8 91.9,4.71 91.95,4.66 | 56.39,31.1 C8.2
  Bottom 0.305: v53.3,31.2 T2.E v53.1,31.1 | v44.4,31.2 T4.E v44.2,31.1 | v35.5,31.2 T6.E v35.3,31.1 | v26.6,31.2 T8.E v26.4,31.1 | T12.E v8.8,31.2 | v17.7,31.2 T10.E v17.6,31
H1
  Top 0.305: 90.68,29.21 86.23,33.66 60.83,33.66 57.03,37.47 R5.1
  Top 0.306: IC2.26 117.35,27.3 114.81,24.77 109.09,24.77 108.46,25.4 94.49,25.4 90.68,29.21
H2
  Top 0.305: R10.1 45.75,37.31 45.59,38.73 46.87,40.01 55.75,40.01 60.83,34.92 86.87,34.92 95.12,26.67 95.76,26.67
  Top 0.306: 95.76,26.67 109.73,26.67 111,26.04 112.91,26.04 IC2.27
L0
  Top 0.305: SS2.0 10.67,71.12 13.21,68.58 18.92,68.58 19.56,69.22 20.2,69.22 22.1,67.94 29.81,67.94 SS1.0 34.22,70.43 36.07,68.58 40.52,68.58 41.15,69.22 44.33,67.94 44.33,67.31 47.5,64.14 58.38,64.14 MM2.0 66.61,70.43 69.09,68.58 73.53,68.58 74.17,69.22 77.98,67.94 78.61,68.58 83.78,68.58 MM1.0 87.5,70.48 89.41,68.58 93.86,68.58 94.49,69.22 97.67,67.94 97.67,66.67 98.3,66.04 114.26,66.04 HH2.0 120.58,70.43 122.43,68.58 126.88,68.58 127.51,69.22 130.69,67.94 130.69,67.31 131.32,66.67 135.22,66.67 HH1.0 147.25,70.43 147.83,69.85 151,67.31 151,65.41 149.1,63.5 147.83,63.5 144.02,59.69 SV3.10
L1
  Top 0.305: SS2.1 19.56,66.04 29.72,66.04 30.35,66.67 arc-37 34.16,69.22 35.44,67.94 40.52,67.94 SS1.1 42.42,66.67 45.59,63.5 59.56,63.5 65.28,68.58 67.19,69.22 68.45,67.94 74.81,67.94 MM2.1 75.44,67.31 84.33,67.31 85.6,68.58 87.5,69.22 88.78,67.94 93.86,67.94 MM1.1 95.76,67.31 98.3,64.77 114.81,64.77 118.62,68.58 120.53,69.22 121.79,67.94 126.88,67.94 HH2.1 128.02,66.8 130.05,64.77 135.13,64.77 138.94,68.58 141.48,69.22 146.56,69.22 HH1.1 141.48,60.26 SV3.9
L2
  Top 0.305: SV3.8 138.94,55.24 149.74,55.24 152.91,58.42 152.91,67.31 150.37,69.85 HH1.2 149.33,71.12 140.84,71.12 140.21,71.75 138.94,72.39 137.67,71.75 136.4,70.48 136.4,69.85 135.13,68.58 131.32,68.58 130.05,69.85 HH2.2 126.82,70.43 126.24,69.85 122.43,69.85 119.25,72.39 117.99,72.39 116.72,71.12 116.72,69.85 113.54,66.67 99.57,66.67 98.94,67.31 98.94,68.17 MM1.2 93.8,70.43 93.22,69.85 89.41,69.85 88.14,71.12 86.23,72.39 84.97,72.39 83.69,71.12 83.69,69.85 76.94,69.85 MM2.2 73.48,70.43 72.9,69.85 69.09,69.85 65.92,72.39 64.64,72.39 63.38,71.12 63.38,70.48 58.3,65.41 48.77,65.41 46.87,67.31 46.23,67.31 44.96,68.81 SS1.2 41.09,70.43 39.88,69.22 36.7,69.22 36.07,69.85 33.53,71.75 32.9,72.39 31.62,72.39 29.72,70.48 21.8,70.48 SS2.2
L3
  Top 0.305: SV3.7 136.4,55.88 137.67,54.61 150.37,54.61 154.18,58.42 154.18,71.12 150.37,74.93 HH1.3 146.97,71.75 141.48,71.75 140.21,73.03 137.03,73.03 135.13,71.12 132.59,71.12 129.83,73.88 HH2.3 129.83,73.44 127.51,71.12 122.43,71.12 121.16,71.75 119.89,73.03 117.35,73.03 116.08,74.3 116.08,76.83 112.27,81.92 101.47,81.92 101.47,79.38 97.03,74.93 | 97.03,74.93 97.03,73.66 94.49,71.12 89.41,71.12 86.87,73.03 78.39,73.03 MM2.3 72.04,70.48 69.72,70.48 68.45,71.75 66.55,73.03 63.38,73.03 61.47,71.12 61.47,70.48 57.66,66.67 48.77,66.67 46.23,69.22 46.23,71.12 43.47,73.88 SS1.3 43.47,74.07 39.24,69.85 37.34,69.85 33.53,73.03 30.99,73.03 29.72,71.75 25.05,71.75 SS2.3 | 97.03,74.93 MM1.3
L4
  Top 0.305: SV3.6 133.86,55.24 135.13,53.98 151,53.98 155.45,58.42 155.45,74.93 150.37,80.01 HH1.4 149.97,79.38 141.48,79.38 140.21,78.11 138.94,77.47 137.67,78.11 137.03,78.74 131.32,78.74 130.63,79.43 HH2.4 129.12,80.01 122.43,80.01 119.89,78.11 118.62,77.47 117.35,78.11 116.72,78.74 113.54,83.19 99.57,83.19 MM1.4 95.7,79.43 95.12,80.01 89.41,80.01 86.87,78.11 85.6,77.47 84.33,78.11 82.42,80.64 77.58,80.64 MM2.4 75.39,79.43 74.81,80.01 69.09,80.01 66.55,78.11 65.28,77.47 64.01,78.11 63.38,78.74 62.74,78.74 60.83,80.64 44.55,80.64 SS1.4 41.78,80.01 36.07,80.01 33.53,78.11 32.26,77.47 31.62,77.47 30.35,78.74 22.44,78.74 SS2.4
L5
  Top 0.305: SS2.5 21.14,83.82 30.99,83.82 31.62,83.19 32.26,81.28 34.16,80.64 34.8,81.28 39.24,81.28 SS1.5 42.49,81.92 64.01,81.92 67.19,80.64 67.82,81.28 72.27,81.28 MM2.5 75.51,81.92 84.33,81.92 87.5,80.64 88.14,81.28 92.58,81.28 MM1.5 97.1,84.45 114.81,84.45 117.35,81.92 120.53,80.64 121.16,81.28 126.24,81.28 127.71,82.75 HH2.5 130.05,82.55 131.32,81.92 131.96,81.28 138.94,81.28 140.84,80.64 142.75,80.64 145.93,81.28 147.83,82.55 HH1.5 149.1,82.55 150.37,82.55 156.72,76.2 156.72,58.42 151.64,53.34 133.22,53.34 131.32,55.24 SV3.5
L6
  Top 0.305: HH1.6 144.09,83.75 142.75,86.36 | 142.75,86.36 126.63,86.36 HH2.6 123.77,83.75 121.16,86.36 93.61,86.36 MM1.6 90.75,83.75 88.14,86.36 73.29,86.36 MM2.6 70.43,83.75 67.82,86.36 40.27,86.36 SS1.6 35.05,86.36 18.29,86.36 16.07,84.14 SS2.6 | 142.75,86.36 148.47,86.36 157.99,76.83 157.99,58.42 152.28,52.7 131.32,52.7 128.78,55.24 SV3.4
L7
  Top 0.305: HH1.7 131.96,82.55 130.69,83.82 128.78,85.09 126.88,85.09 125.6,82.55 124.34,81.92 123.7,81.92 122.43,82.55 HH2.7 119.69,84.02 117.35,85.09 94.49,85.09 92.58,82.55 91.31,81.92 90.05,81.92 89.41,82.55 87.19,82.55 MM1.7 77.78,82.75 75.44,85.09 73.53,85.09 72.27,82.55 71,81.92 70.36,81.92 69.09,82.55 MM2.7 66.35,82.75 65.28,83.82 43.69,83.82 42.42,85.09 40.52,85.09 39.24,82.55 37.98,81.92 36.7,81.92 35.44,82.55 SS1.7 33.33,82.75 30.99,85.09 19.56,85.09 18.29,83.82 17.66,82.55 16.38,81.92 15.75,81.92 14.48,82.55 12.27,82.55 SS2.7 11.94,82.55 9.4,82.55 6.86,80.01 6.86,74.93 5.59,73.66 5.59,57.15 10.67,52.07 121.16,52.07 126.24,57.15 SV3.3
L8
  Top 0.305: HH1.8 131.96,79.38 131.32,80.64 130.69,81.28 129.41,81.28 128.15,80.64 121.79,80.64 119.89,79.38 HH2.8 117.93,79.43 116.08,81.28 114.18,83.82 98.3,83.82 96.39,81.28 94.49,80.64 88.78,80.64 86.87,79.38 MM1.8 84.91,79.43 83.06,81.28 76.08,81.28 74.81,80.64 68.45,80.64 66.55,79.38 MM2.8 63.32,79.43 61.47,81.28 43.05,81.28 41.78,80.64 35.44,80.64 33.53,79.38 SS1.8 32.29,79.98 30.99,81.28 30.99,82.55 22.73,82.55 22.1,81.92 20.2,80.64 11.92,80.64 SS2.8 10.67,78.74 10.67,77.47 6.86,73.66 6.86,57.15 10.67,53.34 119.89,53.34 123.7,57.15 SV3.2
L9
  Top 0.305: HH1.9 132.59,74.93 130.69,76.83 128.15,76.83 125.6,78.11 124.97,78.74 123.06,78.74 121.79,78.11 118.62,76.2 HH2.9 | HH2.9 117.35,74.93 | SV3.1 121.16,57.15 118.62,54.61 10.67,54.61 8.13,57.15 8.13,72.48 SS2.9 11.85,76.2 11.94,76.2 11.94,77.47 14.48,80.01 18.29,80.01 20.83,77.47 29.72,77.47 32.17,75.03 SS1.9 34.16,77.47 36.61,79.38 40.52,79.38 42.42,77.47 44.96,77.47 47.5,74.93 47.5,69.22 48.77,67.94 57.66,67.94 60.2,70.48 60.2,71.12 64.01,74.93 MM2.9 65.92,76.83 69.72,79.38 73.53,79.38 75.44,77.47 83.06,77.47 85.5,75.03 MM1.9 87.5,77.47 89.41,78.74 91.95,78.74 93.86,78.11 95.12,76.83 97.67,76.83 99.57,78.74 100.2,82.55 112.91,82.55 117.35,76.83 117.35,76.11 HH2.9
M1
  Top 0.305: R15.1 36.86,38.89 39.24,41.27 55.75,41.27 60.83,36.2 87.5,36.2 95.76,27.94 98.94,27.94
  Top 0.306: 98.94,27.94 IC2.28
M2
  Top 0.305: R20.1 27.97,41.43 29.09,42.55 55.75,42.55 60.83,37.47 88.14,37.47 95.12,30.48 98.94,30.48
  Top 0.306: IC2.25 119.89,29.21 118.62,30.48 98.94,30.48
N$1
  Top 0.306: R36.2 T14.B
N$2
  Top 0.306: T13.B R35.2
N$3
  Top 0.305: R28.1 12,11.2 12,9.2 SV1.1
N$4
  Top 0.305: R36.1 149.1,27.13 149.8,27.77 150.74,28.7 150.74,35.5 145.3,35.5 IC2.14
  Top 0.306: R36.1 149.1,20.32
N$5
  Top 0.306: R35.1 141.48,24.13 IC2.15
N$6  (via drill 0.5 pad 1.27)
  Top 0.305: U$5.5 83.2,15.8 83.2,12.7 85.6,10.3 C4.1 85.6,10.1 85.5,10.1 81.8,6.4 81.8,5.1 R40.2
  Top 0.306: R40.2 v83.06,5.08
  other vias: 81.79,5.08
N$7  (via drill 0.6 pad 2.54)
  other vias: 114.81,41.91
N$8
  Top 0.305: U$5.2 76.71,18.41 76.08,17.78 73.53,17.78 72.9,18.41 72.9,20.32 71.63,21.59 70.36,21.59 69.09,20.32 69.09,12.7 71.63,10.16 74.17,10.16 75.44,8.89 75.44,6.35 74.17,5.08 72.27,5.08 67.19,10.16 67.19,24.77 Q1.1
  Top 0.306: R38.2 65.91,28.58 66.55,27.94 Q1.1
N$9
  Top 0.305: U$5.3 77.9,17.1 76,17.1 75.5,16.6 C5.1
N$12
  Top 0.305: L1.1 71.63,7.62 68.45,10.79 68.45,25.4 69.09,26.04 73.53,26.04 75.44,24.13 81.79,24.13 83.69,22.23 83.69,21.91 R42.2 | 85.6,20.32 85.6,19.05 84.97,18.41 U$5.7
  Top 0.306: 85.6,20.32 85.6,21.59 84.97,22.23 83.69,22.23 R42.2
N$13  (via drill 0.6 pad 1.93)
  Top 0.306: U$2.A U$1.A 106.87,67.94 102.11,67.94 v100.84,69.22 | SV4.6 24.64,60.96 25.91,62.23 34.8,62.23 38.61,58.42 98.3,58.42 v100.84,60.96
  Bottom 0.306: v100.84,60.96 v100.84,69.22 v100.84,60.96
N$14
  Top 0.305: SV4.4 19.56,62.23 20.83,63.5 36.07,63.5 39.88,59.69 60.2,59.69 66.55,66.04 MM2.A
N$15
  Top 0.305: SV4.2 14.48,63.5 18.29,63.5 19.56,64.77 32.26,64.77 33.53,66.04 SS1.A
N$16
  Top 0.305: SV4.5 22.1,61.59 23.37,62.87 35.44,62.87 39.24,59.05 79.89,59.05 86.87,66.04 MM1.A
N$17
  Top 0.305: R3.2 29.8,14.2 31.2,15.6 50.4,15.6 T1.C
N$18
  Top 0.305: HH2.A 120.02,66.17 117.35,63.5 105.92,63.5 99.57,57.15 37.34,57.15 36.07,58.42 36.07,59.69 34.8,60.96 28.45,60.96 27.18,59.69 SV4.7
N$20
  Top 0.305: R1.2 48.2,22.07 49.41,22.07 50.61,20.86 R2.1 50.8,20.8 53.1,20.8 53.2,20.9 T1.B
N$21  (via drill 0.6)
  Top 0.305: v48.2,31.1 48.2,25 R1.1
  Bottom 0.305: v48.2,31.1 T2.C
N$22  (via drill 0.6)
  Top 0.305: R4.2 51.81,34.97 | R5.2 51.81,37.47 51.81,35.06 R4.2 | v50.7,31.2 50.7,34.8 51.7,34.8 R4.2
  Bottom 0.305: T2.B v50.7,31.2
N$23
  Top 0.305: HH1.A 140.01,67.11 137.03,64.14 | 120.53,64.14 118.62,62.23 107.19,62.23 100.84,55.88 30.99,55.88 29.72,57.15 SV4.8
  Top 0.306: 120.53,64.14 137.03,64.14
N$24
  Top 0.305: T3.C 44.3,18.4 42.2,16.3 29.4,16.3 27.3,14.2 R8.2
  Top 0.306: R33*.2 R8.2
N$25  (via drill 0.6)
  Top 0.305: R6.2 39.3,22.07 40.51,22.07 41.7,20.86 R7.1 41.91,20.86 v44.3,20.86
  Bottom 0.305: v44.3,20.86 T3.B
N$26  (via drill 0.6)
  Top 0.305: v39.3,31.1 39.3,25 R6.1
  Bottom 0.305: v39.3,31.1 T4.C
N$27  (via drill 0.6)
  Top 0.305: R10.2 42.91,34.97 R9.2 42.8,34.9 41.8,34.9 v41.8,31.2
  Bottom 0.305: T4.B v41.8,31.2
N$28
  Top 0.305: R23.1 14.5,11.2 14.5,9.2 SV1.2
N$29
  Top 0.305: R13.2 22.1,14.2 24.9,17 34,17 35.4,18.4 T5.C
N$30
  Top 0.305: R11.2 30.41,22.07 31.6,22.07 32.8,20.86 R12.1 33,20.9 35.4,20.9 T5.B
N$31  (via drill 0.6)
  Top 0.305: v30.4,31.1 30.4,25 R11.1
  Bottom 0.305: v30.4,31.1 T6.C
N$32  (via drill 0.6)
  Top 0.305: R15.2 34.1,37.47 34.1,34.97 R14.2 33.9,34.9 32.9,34.9 v32.9,31.2
  Bottom 0.305: T6.B v32.9,31.2
N$33
  Top 0.305: SV4.1 11.94,66.04 SS2.A
N$34
  Top 0.306: SV1.9 R41*.1
N$35
  Top 0.305: R16.2 21.51,22.07 22.8,22.07 24.01,20.86 R17.1 24.1,20.9 26.5,20.9 T7.B
N$36  (via drill 0.6)
  Top 0.305: v21.5,31.1 21.5,25 R16.1
  Bottom 0.305: v21.5,31.1 T8.C
N$37  (via drill 0.6)
  Top 0.305: R20.2 25.2,37.47 25.2,34.97 R19.2 25,34.9 24.1,34.9 v24.1,31.2
  Bottom 0.305: T8.B v24.1,31.2
N$38
  Top 0.305: R34*.1 17.1,11.2 17.1,9.2 SV1.3
N$39
  Top 0.305: R23.2 14.5,14.2 17.6,17.3 17.6,18.4 T9.C
N$40
  Top 0.305: R21.2 12.61,22.07 13.91,22.07 15.11,20.86 R22.1 15.2,20.9 17.6,20.9 T9.B
N$41  (via drill 0.6)
  Top 0.305: v12.6,31.1 12.6,25 R21.1
  Bottom 0.305: v12.6,31.1 T10.C
N$42  (via drill 0.6)
  Top 0.305: R25.2 16.3,37.47 16.3,34.97 R24.2 16.1,34.9 15.2,34.9 v15.2,31.2
  Bottom 0.305: T10.B v15.2,31.2
N$43
  Top 0.305: R18.1 19.6,11.2 19.6,9.2 SV1.4
N$44
  Top 0.305: R28.2 11.9,14.2 8.8,17.3 8.8,18.4 T11.C
N$45
  Top 0.305: R26.2 3.7,22.07 4.91,20.86 6.11,20.86 R27.1 6.3,20.9 8.7,20.9 T11.B
N$46  (via drill 0.6)
  Top 0.305: v3.7,31.1 3.7,25 R26.1
  Bottom 0.305: v3.7,31.1 T12.C
N$47  (via drill 0.6)
  Top 0.305: R30.2 7.41,37.47 7.41,34.97 R29.2 7.2,34.9 6.3,34.9 v6.3,31.2
  Bottom 0.305: T12.B v6.3,31.2
N$48  (via drill 0.5 pad 1.27)
  Top 0.305: R37.2 78,10 78,8.9 79.2,7.7 R40.3 v77.98,7.62 77.98,10.16
N$49
  Top 0.305: SV1.5 R13.1
N$50  (via drill 0.5 pad 1.27)
  Top 0.305: R40.1 v77.98,2.54 64.01,2.54 58.93,7.62 R39.1
N$51  (via drill 0.6 pad 1.93)
  Top 0.306: SV4.3 17.02,60.96 20.2,64.14 36.7,64.14 39.88,60.96 49.41,60.96 v50.04,61.59 | v50.04,71.75 51.63,71.75 U$3.A
  Top 0.406: U$3.A U$4.A
  Bottom 0.306: v50.04,61.59 v50.04,71.75
N$52
  Top 0.305: R8.1 27.2,11.2 27.2,9.2 SV1.7
N$53
  Top 0.305: R3.1 29.8,11.2 29.8,9.2 SV1.8
N$54
  Top 0.305: IC2.2 114.8,35.6 109.8,40.6 107.2,40.6 SV2.2
N$55
  Top 0.305: IC2.3 117.3,35.6 111.6,41.3 109.1,41.3 107.3,43.1 107.2,43.1 SV2.3
N$56
  Top 0.305: S1.1 146.9,45.7 S6.3
  Top 0.306: S6.3 147.75,45.8 149.1,44.45 149.1,40.64 148.19,40.64 S6.4 | S6.4 146.48,39.29 | IC2.13 142.75,38.1 144.02,39.37 146.76,39.37 S6.4
N$57
  Top 0.305: S2.1 S5.3
  Top 0.306: S2.1 141.2,45.44 | S2.1 S5.3 | IC2.12 141.2,36.55 S5.4 141.48,39.57 141.48,40.64 140.21,41.91 140.21,44.7 S2.1
N$58
  Top 0.305: S4.3 131.1,45.8 S3.1
  Top 0.306: S3.1 131.04,45.44 130.05,44.45 130.05,40.28 S4.4 131.12,39.37 137.03,41.91 138.31,40.64 138.31,38.1 137.67,37.47 IC2.11
N$59
  Top 0.305: IC1.7 137.67,22.86 138.94,22.86 142.75,26.67 IC2.16
N$60
  Top 0.306: IC2.17 140.21,26.67 136.4,22.86 133.86,22.86 132.59,21.59 IC1.6
N$61
  Top 0.306: IC1.4 130.05,22.86 132.59,22.86 133.86,24.13 135.13,24.13 137.67,26.67 IC2.18
N$62
  Top 0.306: IC2.19 131.32,24.13 128.15,24.13 124.97,20.95 IC1.3 124.97,19.68
N$63
  Top 0.305: IC2.10 135.2,35.5 135.2,33.2 R32.2 135.3,33.1 135.4,33 148.5,33 IC4.5
N$64
  Top 0.305: IC2.9 132.5,35.5 131.4,34.23 131.4,33.2 R31.2 131.5,33.1 132.7,31.9 148.4,31.9 148.5,31.8 IC4.6
N$65
  Top 0.306: IC4.1 154.71,28.68 154.18,27.94 Q2.2
N$66
  Top 0.306: IC4.2 156.72,30.48 Q2.1
N$67
  Top 0.306: IC4.3 156.72,31.75 157.99,30.48 157.99,8.89 151.64,2.54 81.79,2.54 80.52,1.27 15.75,1.27 8.13,8.89 8.13,13.97 1.78,20.32 1.78,34.92 13.21,46.35 98.24,46.35 G1.+
N$68
  Top 0.306: SV1.6 R33*.1
N$70
  Top 0.306: 132.59,43.18 135.13,43.18 136.4,45.72
N$71
  Top 0.305: IC2.6 124.9,35.6 121.2,39.3 SV6.1 121.2,39.5 121.2,41.9 SG1.+
N$72
  Top 0.305: R34*.2 R18.2 19.7,14.1 23.3,17.7 25.8,17.7 26.5,18.4 T7.C
N$73  (via drill 0.6 pad 1.93)
  other vias: 53.22,78.74
N$74
  Top 0.3: 77.98,22.23 79.25,22.23
N$75
  Top 0.3: 81.79,22.23 83.06,22.23
N$76  (via drill 0.6 pad 1.93)
  other vias: 57.03,78.74
N$77  (via drill 0.6 pad 1.93)
  other vias: 53.22,69.85
N$78  (via drill 0.6 pad 1.93)
  other vias: 57.03,69.85
N$79  (via drill 0.6 pad 1.93)
  other vias: 105.28,78.74
N$80  (via drill 0.6 pad 1.93)
  other vias: 109.09,78.74
N$81  (via drill 0.6 pad 1.93)
  other vias: 105.28,69.85
N$82  (via drill 0.6 pad 1.93)
  other vias: 109.09,69.85
N$86  (via drill 0.6 pad 1.68)
  other vias: 127.51,23.5
N$87  (via drill 0.6 pad 1.68)
  other vias: 138.31,24.77
N$89  (via drill 0.6 pad 1.68)
  other vias: 135.76,24.77
N$90  (via drill 0.6 pad 1.68)
  Top 0.305: v111,37.47 109.73,35.56 IC2.1
  Top 0.406: R43.2 IC2.1
N$92  (via drill 0.6 pad 2.18)
  Top 0.305: Q1.2 63.9,25.3 | D1.A 53.85,7.62 | v64.01,7.62 62.11,9.53 62.11,13.97
  Top 0.306: L1.2 53.85,7.62 53.85,12.7 60.2,12.7 62.11,13.97 62.11,22.23 64.01,24.13 Q1.2
N$95
  Top 0.306: 142.75,43.18 145.29,43.18
NEON1  (via drill 0.6 pad 1.93)
  Top 0.306: SV3.12 149.1,59.69 v151,62.23 | v140.84,62.23 120.53,62.23 117.99,59.69 v113.54,59.69 | v113.54,76.2 113.54,78.11 111,80.64 106.56,80.64 105.92,80.01 105.92,79.06 U$2.K 103.38,78.74 v102.11,77.47 | U$4.K 57.98,77.47 v58.93,77.47
  Bottom 0.306: v140.84,62.23 v151,62.23 | v113.54,76.2 v113.54,59.69 | v58.93,77.47 v102.11,77.47
NEON2  (via drill 0.6 pad 1.93)
  Top 0.306: U$1.K 105.6,70.17 | SV3.11 146.56,57.15 145.29,55.88 141.48,55.88 140.21,57.15 140.21,59.69 138.94,60.96 121.16,60.96 117.35,57.15 v107.19,57.15 | v107.19,72.39 105.6,70.8 U$1.K | U$1.K 103.06,72.39 v102.11,72.39 | v58.93,72.39 56.71,70.17 U$3.K
  Bottom 0.306: v107.19,72.39 v107.19,57.15 | v58.93,72.39 v102.11,72.39
S1
  Top 0.305: R25.1 19.1,37.47 25.44,43.8 56.07,43.8 61.13,38.74 88.78,38.73 95.76,31.75 99.87,31.75
  Top 0.306: IC2.24 122.43,30.48 121.16,31.75 99.87,31.75
S2
  Top 0.305: R30.1 10.19,37.62 17.66,45.09 56.39,45.09 61.47,40.01 89.41,40.01 96.39,33.02 100.2,33.02
  Top 0.306: 100.2,33.02 122.43,33.02 124.97,30.48 IC2.23
VCC  (via drill 0.6 pad 1.68)
  Top 0.305: R31.1 131.4,30.3 131.4,27.94 | R32.1 135.2,30.3 135.2,29.84 | 93.86,24.13 93.22,24.13 84.97,32.38 77.98,32.38 IC3.3 | 107.19,35.56 107.19,33.66 127.51,33.66 | C10.1 117.99,22.23 118.62,22.86 | SV2.1 107.2,35.7 R43.1 | 123.7,22.86 v123.7,24.13
  Top 0.306: 93.86,24.13 105.28,24.13 106.56,22.86 C7.+ 118.62,22.86 123.7,22.86 | IC2.20 131.4,27.94 IC2.21 | IC2.20 132.59,29.84 135.2,29.84 146.56,29.84 147.19,29.21 IC4.8 | IC1.5 130.05,17.78 124.97,17.78 123.7,19.05 123.7,22.86 | 123.7,22.86 126.24,25.4 | 126.24,25.4 131.32,25.4 132.59,26.67 IC2.20 | IC2.7 127.51,33.66 C9.1 127.51,33.02 126.24,31.75 126.24,25.4
  Top 0.406: 107.19,35.56 R43.1
VCC+12
  Top 0.305: 83.2,19.6 U$5.8 83,19.7 80.52,19.7 | J1.3 111,13.2 | 78,19.7 80.52,19.7 | 78,19.7 U$5.1 77.8,19.6 77,19.6 76.5,19.1 75.5,19.1 C3.1 | U$5.6 83.2,17.1 | 88.14,17.1 88.93,17.1 | IC3.1 84.33,27.94 86.87,25.4 86.87,18.37 88.14,17.1 | 88.14,17.1 83.17,17.1 U$5.6 | U$5.6 81.16,17.14 80.52,17.78 80.52,19.7 | 78,19.7 78,21.26 R42.1 74.17,22.23 C6.+
  Top 0.306: 88.93,17.1 90.2,15.72 C2.+
  Top 0.406: J1.3 91.95,13.16 C2.+
VDD
  Top 0.305: R7.2 41.63,23.5 | R27.2 6.3,23.6 6.4,23.5 8.7,23.5 T11.E 8.9,23.5 9,23.6 15,23.6 R22.2 15.2,23.6 15.3,23.5 17.6,23.5 T9.E 17.8,23.5 23.8,23.5 23.9,23.6 R17.2 24.1,23.6 24.2,23.5 26.5,23.5 T7.E 26.6,23.5 32.8,23.5 R12.2 32.9,23.6 33,23.5 35.4,23.5 T5.E 35.5,23.5 41.5,23.5 R7.2 | R39.2 59,14.2 60.2,14.2 C1.+ 60.1,20.4 57.1,23.4 56.39,23.4 53.3,23.4 T1.E 53.2,23.5 50.8,23.5 50.7,23.6 R2.2 50.6,23.6 44.4,23.6 T3.E 44.3,23.5 42,23.5 41.9,23.6 R7.2
  Top 0.306: 34.8,13.97 32.26,13.97 R41*.2 | 34.8,13.97 39.88,8.89 39.88,5.08 D1.C | 34.8,13.97 58.93,13.97 R39.2
  Top 0.406: 56.39,23.4 C8.1
(copper drawn outside any net)
  shapes: Top area x6

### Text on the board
Top: IN-12B Nixie Clock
